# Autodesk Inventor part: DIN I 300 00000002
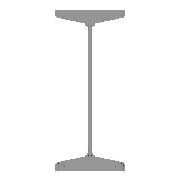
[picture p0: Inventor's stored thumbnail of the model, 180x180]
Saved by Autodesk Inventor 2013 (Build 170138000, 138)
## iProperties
IsCustomPart: 1
Created: 2009-11
Part Number: DIN I 300 00000002
Material: Steel, Mild
Description: Hot rolled I-beam
Document SubType Name: Modeling
Standard: DIN
Designer: pokornp
Standard Revision: 1995
Standards Organization: DIN
Language: en-US
Size Designation: I 300
Categories: <MemberInstance><Categories><Category DisplayName="Structural Shapes" InternalName="089c4875-fa83-4c05-b084-43b9cc11f5ed" Mnemonic="GRDR"><CategoryParameter Dis
Stock Number: I 300
Density: 7.86 g/cm^3
Sheet Metal Rule: Default
_CCFamilyMember: 120
_CCFamilyDisplayName: DIN 1025-1 - Hot rolled I-beam
_FrameMemberDoc: Frame Member File
_Version: 15.0.0
G_L: 10000.000 mm
G_W: 125.000 mm
G_H: 300.000 mm
Author: pokornp
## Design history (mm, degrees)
node "Start plane"
node "End plane"
sketch "Sketch"
  geometry: L1 (5.4, -120.788)-(5.4, 120.788); L2 (-62.5, -150)-(62.5, -150); L3 (-5.4, 120.788)-(-5.4, -120.788); L4 (62.5, 150)-(-62.5, 150); L5 (0, -210)-(0, 210) reference; L6 (-89.185, 0)-(89.185, 0) reference; L7 (-62.5, 150)-(-62.5, 143.828); L8 (-56.901, 137.391)-(-14.703, 131.483); L9 (62.5, 150)-(62.5, 143.828); L10 (56.901, 137.391)-(14.703, 131.483); L11 (-56.901, -137.391)-(-14.703, -131.483); L12 (14.703, -131.483)-(56.901, -137.391); L13 (62.5, -143.828)-(62.5, -150); L14 (-62.5, -150)-(-62.5, -143.828); A1 r 6.5 centre (-56, 143.828) between (-62.5, 143.828) and (-56.901, 137.391); A2 r 6.5 centre (56, 143.828) between (56.901, 137.391) and (62.5, 143.828); A3 r 6.5 centre (56, -143.828) between (62.5, -143.828) and (56.901, -137.391); A4 r 6.5 centre (-56, -143.828) between (-56.901, -137.391) and (-62.5, -143.828); A5 r 10.8 centre (-16.2, 120.788) between (-5.4, 120.788) and (-14.703, 131.483); A6 r 10.8 centre (16.2, 120.788) between (14.703, 131.483) and (5.4, 120.788); A7 r 10.8 centre (16.2, -120.788) between (5.4, -120.788) and (14.703, -131.483); A8 r 10.8 centre (-16.2, -120.788) between (-14.703, -131.483) and (-5.4, -120.788); 6 further points
  constraints: 24 end point, 16 point on circle, 16 tangent, 9 point on line, 8 centre point, 6 equal radius, 4 equal length, 3 parallel, 2 horizontal, 2 vertical, 1 perpendicular, 1 symmetric about line, 3 other
  dimensions: "d3" = 300 vertical distance of L2.end L4.end (= ParH); "d17" = 125 distance of L4.start L4.end (= b); "d22" = 10.8 distance between parallel lines of L3 L1 (= t1); "d28" = 150 distance between parallel lines of L2 L6 (= 0.5 x d3); "d31" = 7.96961 deg angle of L4 L8; "d32" = 31.25 distance from line of point (31.25, -133.8) L13 (= 0.25 x b); "d33" = 16.2 distance from line of L2 point (31.25, -133.8) (= t2); "d34" = 6.5 radius of A1 (= R1); "d35" = 10.8 radius of A5 (= R)
extrude "Body" new body sketch "Sketch" stored distance "d18" = 10000 (= G_L); taper "d19" = 0 deg
node "Driven Length"
  sketch "Sketch3"
    geometry: L1 (0, 0)-(10, 0) reference
    constraints: 2 end point, 1 horizontal
  workplane "Work Plane7"
  sketch "Sketch4"
    geometry: L1 (-2, 0)-(12, 0) reference; L2 (-2, 10000)-(12, 10000) reference
    dimensions: "d37" = 10000 distance between parallel lines of L1 L2 (derived)
body "Solid1"
other parameters: "b" = 125 [user parameter; used in 4 equation terms], "ParH" = 300 [user parameter; used in 1 equation term], "R1" = 6.5 [user parameter; used in 1 equation term], "t1" = 10.8 [user parameter; used in 2 equation terms], "t2" = 16.2 [user parameter; used in 1 equation term], "msp_pom" = 51.7 (= 0.5 x b - t1) [user parameter; used in 1 equation term], "msp_x1" = 3.619 (= 0.07 x msp_pom) [user parameter], "msp_x2" = 4.375 (= 0.035 x b) [user parameter], "G_L" = 10000 (= d37) [user parameter; used in 1 equation term], "R" = 10.8 [user parameter; used in 1 equation term], "d4" = 4.25 (derived), "d6" = 7.47 (derived), "d8" = 0 (derived), "d10" = 0 (derived), "d12" = 4.25 (derived), "d14" = 4.25 (derived), "G_OFFSET_START" = 0 [user parameter; used in 1 equation term], "G_OFFSET_END" = 0 [user parameter; used in 1 equation term], "d29" = 0 (computed from G_OFFSET_START), "Thickness" = 0.5, "BendRadius" = 0.5 (= Thickness), "BendReliefWidth" = 0.5 (= Thickness), "BendReliefDepth" = 0.25 (= 0.5 x Thickness), "CornerReliefSize" = 2 (= 4 x Thickness), "SeamGap" = 0.01, "MinimumRemnant" = 1 (= 2 x Thickness), "TransitionRadius" = 0.5 (= BendRadius), "JacobiRadiusSize" = 0.5 (= Thickness), "d36" = 90 deg, "GapSize" = 0.5 (= Thickness)
